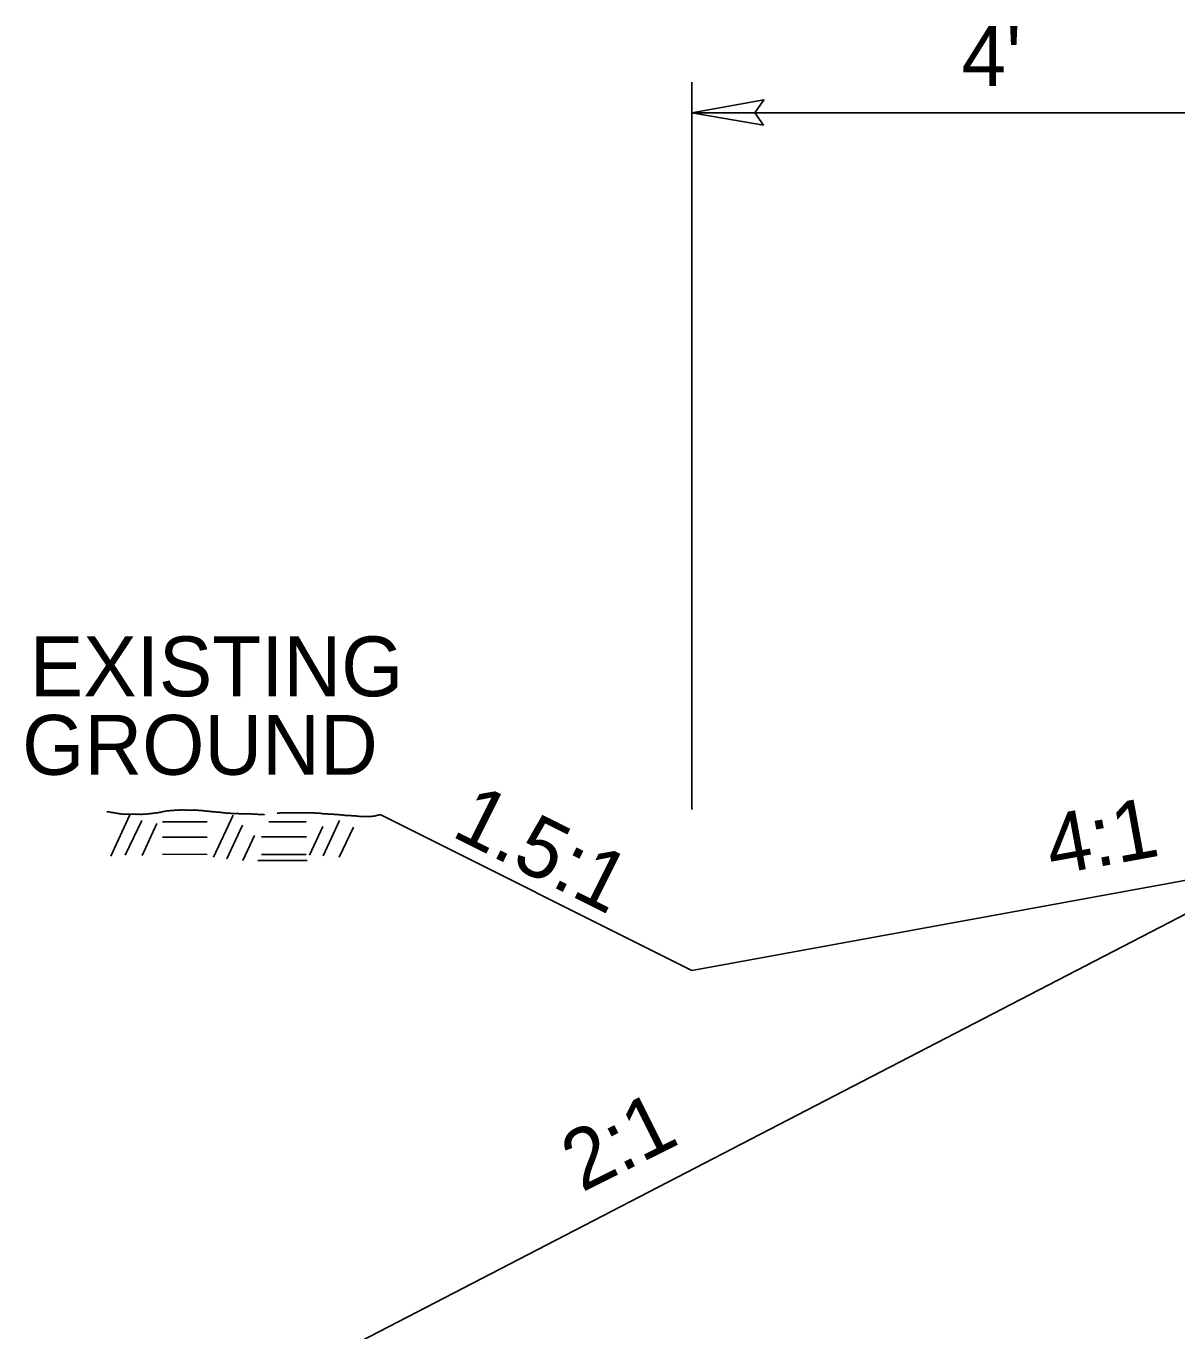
# Model space of a CAD drawing. Extents: x 1542177 to 1542464, y 45134 to 45344.
# Drawn here: x 1542276.79 to 1542288.32, y 45194.34 to 45207.43 of the extents above; entities that cross this region are included whole.
import ezdxf

# ---------------------------------------------------------------- set-up
doc = ezdxf.new("R2010")
doc.units = 0
doc.layers.add('Default', color=7, linetype='Continuous')

msp = doc.modelspace()

# ---------------------------------------------------------------- linework, layer by layer
at = {"layer": 'Default'}
for p, q in [((1542283.461, 45199.571), (1542283.461, 45206.867)), ((1542283.461, 45206.56), (1542289.373, 45206.56)), ((1542277.829, 45199.518), (1542277.638, 45199.104)), ((1542277.947, 45199.462), (1542277.782, 45199.114)), ((1542278.1, 45199.431), (1542277.952, 45199.112)), ((1542278.156, 45199.449), (1542278.603, 45199.448)), ((1542278.863, 45199.515), (1542278.666, 45199.093)), ((1542278.958, 45199.416), (1542278.802, 45199.078)), ((1542279.221, 45199.448), (1542279.597, 45199.448)), ((1542279.763, 45199.402), (1542279.628, 45199.113)), ((1542279.931, 45199.46), (1542279.766, 45199.106)), ((1542280.069, 45199.396), (1542279.928, 45199.093)), ((1542283.461, 45197.957), (1542280.336, 45199.52)), ((1542278.156, 45199.296), (1542278.604, 45199.296)), ((1542279.077, 45199.31), (1542278.961, 45199.06)), ((1542279.147, 45199.297), (1542279.598, 45199.297)), ((1542278.156, 45199.123), (1542278.604, 45199.122)), ((1542278.251, 45193.26), (1542289.419, 45199.047)), ((1542279.111, 45199.06), (1542279.605, 45199.06)), ((1542279.148, 45199.121), (1542279.596, 45199.121)), ((1542289.419, 45199.047), (1542283.461, 45197.957))]:
    msp.add_line(p, q, dxfattribs=at)
msp.add_lwpolyline([(1542284.181, 45206.436), (1542283.461, 45206.56), (1542284.185, 45206.688), (1542284.093, 45206.56)], close=True, dxfattribs=at)
for points in [[(1542277.599, 45199.547), (1542277.6, 45199.548), (1542277.601, 45199.549), (1542277.602, 45199.549), (1542277.604, 45199.55), (1542277.606, 45199.549), (1542277.608, 45199.549), (1542277.611, 45199.549), (1542277.614, 45199.55), (1542277.616, 45199.55), (1542277.619, 45199.549), (1542277.62, 45199.548), (1542277.623, 45199.547), (1542277.625, 45199.547), (1542277.627, 45199.546), (1542277.63, 45199.545), (1542277.633, 45199.545), (1542277.635, 45199.544), (1542277.638, 45199.544), (1542277.64, 45199.543), (1542277.642, 45199.542), (1542277.644, 45199.542), (1542277.646, 45199.541), (1542277.649, 45199.542), (1542277.652, 45199.542), (1542277.654, 45199.542), (1542277.657, 45199.54), (1542277.659, 45199.54), (1542277.662, 45199.54), (1542277.664, 45199.541), (1542277.667, 45199.54), (1542277.669, 45199.54), (1542277.672, 45199.539), (1542277.674, 45199.538), (1542277.676, 45199.538), (1542277.679, 45199.537), (1542277.681, 45199.536), (1542277.683, 45199.536), (1542277.686, 45199.535), (1542277.688, 45199.535), (1542277.691, 45199.535), (1542277.693, 45199.535), (1542277.696, 45199.535), (1542277.698, 45199.534), (1542277.7, 45199.534), (1542277.702, 45199.533), (1542277.705, 45199.532), (1542277.707, 45199.532), (1542277.71, 45199.531), (1542277.712, 45199.531), (1542277.715, 45199.532), (1542277.717, 45199.531), (1542277.72, 45199.53), (1542277.722, 45199.53), (1542277.724, 45199.529), (1542277.727, 45199.529), (1542277.729, 45199.528), (1542277.731, 45199.528), (1542277.734, 45199.527), (1542277.738, 45199.528), (1542277.741, 45199.528), (1542277.743, 45199.528), (1542277.745, 45199.526), (1542277.748, 45199.526), (1542277.752, 45199.525), (1542277.755, 45199.525), (1542277.759, 45199.526), (1542277.761, 45199.526), (1542277.764, 45199.526), (1542277.766, 45199.526), (1542277.769, 45199.526), (1542277.773, 45199.525), (1542277.776, 45199.525), (1542277.779, 45199.524), (1542277.781, 45199.524), (1542277.783, 45199.524), (1542277.787, 45199.524), (1542277.79, 45199.524), (1542277.794, 45199.524), (1542277.796, 45199.524), (1542277.799, 45199.524), (1542277.802, 45199.524), (1542277.805, 45199.524), (1542277.809, 45199.524), (1542277.813, 45199.524), (1542277.816, 45199.523), (1542277.82, 45199.524), (1542277.823, 45199.524), (1542277.826, 45199.524), (1542277.828, 45199.524), (1542277.831, 45199.525), (1542277.833, 45199.525), (1542277.835, 45199.524), (1542277.838, 45199.524), (1542277.841, 45199.524), (1542277.844, 45199.524), (1542277.848, 45199.524), (1542277.852, 45199.524), (1542277.856, 45199.524), (1542277.86, 45199.524), (1542277.862, 45199.524), (1542277.864, 45199.524), (1542277.866, 45199.524), (1542277.869, 45199.524), (1542277.873, 45199.524), (1542277.876, 45199.524), (1542277.879, 45199.524), (1542277.882, 45199.524), (1542277.885, 45199.524), (1542277.887, 45199.524), (1542277.889, 45199.523), (1542277.891, 45199.523), (1542277.894, 45199.523), (1542277.896, 45199.524), (1542277.898, 45199.524), (1542277.9, 45199.524), (1542277.902, 45199.524), (1542277.905, 45199.524), (1542277.907, 45199.524), (1542277.909, 45199.524), (1542277.912, 45199.524), (1542277.914, 45199.524), (1542277.917, 45199.524), (1542277.919, 45199.524), (1542277.922, 45199.524), (1542277.925, 45199.523), (1542277.927, 45199.523), (1542277.929, 45199.523), (1542277.932, 45199.523), (1542277.934, 45199.523), (1542277.936, 45199.523), (1542277.938, 45199.524), (1542277.94, 45199.524), (1542277.944, 45199.524), (1542277.948, 45199.523), (1542277.952, 45199.523), (1542277.954, 45199.523), (1542277.957, 45199.524), (1542277.959, 45199.524), (1542277.961, 45199.524), (1542277.963, 45199.524), (1542277.964, 45199.524), (1542277.969, 45199.524), (1542277.973, 45199.525), (1542277.977, 45199.526), (1542277.979, 45199.526), (1542277.981, 45199.526), (1542277.984, 45199.526), (1542277.987, 45199.526), (1542277.99, 45199.525), (1542277.994, 45199.525), (1542277.998, 45199.525), (1542278.002, 45199.528), (1542278.006, 45199.528), (1542278.009, 45199.528), (1542278.013, 45199.527), (1542278.016, 45199.527), (1542278.02, 45199.528), (1542278.023, 45199.528), (1542278.027, 45199.529), (1542278.03, 45199.53), (1542278.034, 45199.531), (1542278.037, 45199.531), (1542278.04, 45199.532), (1542278.044, 45199.531), (1542278.048, 45199.531), (1542278.05, 45199.532), (1542278.052, 45199.532), (1542278.055, 45199.533), (1542278.057, 45199.533), (1542278.06, 45199.534), (1542278.062, 45199.535), (1542278.066, 45199.535), (1542278.07, 45199.534), (1542278.074, 45199.535), (1542278.076, 45199.535), (1542278.079, 45199.535), (1542278.081, 45199.536), (1542278.084, 45199.536), (1542278.086, 45199.538), (1542278.088, 45199.538), (1542278.09, 45199.538), (1542278.092, 45199.538), (1542278.094, 45199.538), (1542278.1, 45199.539), (1542278.106, 45199.538), (1542278.111, 45199.54), (1542278.114, 45199.54), (1542278.117, 45199.541), (1542278.119, 45199.542), (1542278.122, 45199.542), (1542278.124, 45199.543), (1542278.127, 45199.544), (1542278.129, 45199.544), (1542278.131, 45199.543), (1542278.134, 45199.543), (1542278.137, 45199.544), (1542278.141, 45199.546), (1542278.145, 45199.547), (1542278.147, 45199.547), (1542278.15, 45199.547), (1542278.152, 45199.547), (1542278.156, 45199.548), (1542278.158, 45199.55), (1542278.162, 45199.551), (1542278.164, 45199.551), (1542278.167, 45199.55), (1542278.169, 45199.551), (1542278.172, 45199.551), (1542278.174, 45199.552), (1542278.176, 45199.553), (1542278.178, 45199.553), (1542278.181, 45199.554), (1542278.183, 45199.555), (1542278.186, 45199.555), (1542278.189, 45199.556), (1542278.191, 45199.556), (1542278.195, 45199.557), (1542278.198, 45199.557), (1542278.202, 45199.557), (1542278.204, 45199.558), (1542278.207, 45199.558), (1542278.209, 45199.558), (1542278.211, 45199.558), (1542278.213, 45199.56), (1542278.215, 45199.56), (1542278.218, 45199.56), (1542278.22, 45199.56), (1542278.223, 45199.56), (1542278.226, 45199.56), (1542278.228, 45199.56), (1542278.23, 45199.56), (1542278.234, 45199.56), (1542278.237, 45199.561), (1542278.241, 45199.561), (1542278.244, 45199.561), (1542278.246, 45199.561), (1542278.249, 45199.561), (1542278.251, 45199.561), (1542278.252, 45199.563), (1542278.254, 45199.563), (1542278.258, 45199.563), (1542278.263, 45199.563), (1542278.267, 45199.563), (1542278.269, 45199.563), (1542278.271, 45199.563), (1542278.273, 45199.563), (1542278.275, 45199.564), (1542278.277, 45199.565), (1542278.28, 45199.565), (1542278.282, 45199.565), (1542278.285, 45199.565), (1542278.287, 45199.565), (1542278.29, 45199.565), (1542278.292, 45199.565), (1542278.294, 45199.565), (1542278.296, 45199.565), (1542278.299, 45199.565), (1542278.301, 45199.565), (1542278.303, 45199.565), (1542278.305, 45199.565), (1542278.307, 45199.565), (1542278.31, 45199.565), (1542278.313, 45199.566), (1542278.316, 45199.567), (1542278.318, 45199.567), (1542278.32, 45199.566), (1542278.322, 45199.566), (1542278.325, 45199.566), (1542278.328, 45199.567), (1542278.331, 45199.567), (1542278.332, 45199.567), (1542278.334, 45199.566), (1542278.336, 45199.566), (1542278.34, 45199.566), (1542278.345, 45199.567), (1542278.349, 45199.567), (1542278.353, 45199.567), (1542278.357, 45199.567), (1542278.361, 45199.567), (1542278.364, 45199.567), (1542278.367, 45199.566), (1542278.369, 45199.566), (1542278.376, 45199.566), (1542278.384, 45199.567), (1542278.391, 45199.567), (1542278.393, 45199.567), (1542278.395, 45199.566), (1542278.397, 45199.566), (1542278.399, 45199.566), (1542278.402, 45199.566), (1542278.404, 45199.566), (1542278.407, 45199.566), (1542278.409, 45199.566), (1542278.411, 45199.566), (1542278.414, 45199.566), (1542278.416, 45199.566), (1542278.419, 45199.566), (1542278.423, 45199.566), (1542278.426, 45199.566), (1542278.43, 45199.566), (1542278.433, 45199.566), (1542278.435, 45199.566), (1542278.438, 45199.566), (1542278.44, 45199.566), (1542278.442, 45199.566), (1542278.445, 45199.566), (1542278.447, 45199.566), (1542278.449, 45199.566), (1542278.452, 45199.566), (1542278.454, 45199.566), (1542278.456, 45199.566), (1542278.459, 45199.566), (1542278.461, 45199.566), (1542278.463, 45199.566), (1542278.466, 45199.566), (1542278.468, 45199.566), (1542278.47, 45199.567), (1542278.473, 45199.567), (1542278.475, 45199.567), (1542278.477, 45199.567), (1542278.479, 45199.567), (1542278.482, 45199.566), (1542278.486, 45199.565), (1542278.49, 45199.565), (1542278.492, 45199.565), (1542278.495, 45199.565), (1542278.498, 45199.565), (1542278.5, 45199.565), (1542278.502, 45199.565), (1542278.505, 45199.565), (1542278.507, 45199.565), (1542278.509, 45199.565), (1542278.511, 45199.565), (1542278.514, 45199.565), (1542278.516, 45199.563), (1542278.518, 45199.563), (1542278.521, 45199.563), (1542278.524, 45199.563), (1542278.526, 45199.563), (1542278.529, 45199.563), (1542278.531, 45199.563), (1542278.534, 45199.563), (1542278.537, 45199.563), (1542278.541, 45199.563), (1542278.544, 45199.563), (1542278.547, 45199.562), (1542278.549, 45199.561), (1542278.552, 45199.561), (1542278.554, 45199.561), (1542278.556, 45199.561), (1542278.558, 45199.561), (1542278.56, 45199.56), (1542278.563, 45199.559), (1542278.565, 45199.559), (1542278.581, 45199.557), (1542278.596, 45199.555), (1542278.611, 45199.554), (1542278.614, 45199.554), (1542278.616, 45199.554), (1542278.618, 45199.554), (1542278.621, 45199.554), (1542278.624, 45199.552), (1542278.626, 45199.552), (1542278.628, 45199.552), (1542278.63, 45199.552), (1542278.632, 45199.552), (1542278.635, 45199.552), (1542278.637, 45199.553), (1542278.64, 45199.552), (1542278.642, 45199.552), (1542278.645, 45199.551), (1542278.647, 45199.551), (1542278.649, 45199.55), (1542278.652, 45199.55), (1542278.654, 45199.55), (1542278.66, 45199.55), (1542278.666, 45199.55), (1542278.672, 45199.55), (1542278.675, 45199.55), (1542278.677, 45199.549), (1542278.68, 45199.549), (1542278.682, 45199.548), (1542278.684, 45199.549), (1542278.687, 45199.548), (1542278.689, 45199.548), (1542278.692, 45199.547), (1542278.694, 45199.546), (1542278.702, 45199.546), (1542278.71, 45199.546), (1542278.718, 45199.545), (1542278.725, 45199.544), (1542278.732, 45199.544), (1542278.739, 45199.543), (1542278.743, 45199.543), (1542278.746, 45199.542), (1542278.75, 45199.542), (1542278.754, 45199.541), (1542278.758, 45199.54), (1542278.761, 45199.54), (1542278.764, 45199.539), (1542278.767, 45199.54), (1542278.769, 45199.54), (1542278.771, 45199.54), (1542278.774, 45199.538), (1542278.776, 45199.538), (1542278.778, 45199.537), (1542278.78, 45199.538), (1542278.782, 45199.538), (1542278.785, 45199.538), (1542278.787, 45199.536), (1542278.79, 45199.536), (1542278.793, 45199.536), (1542278.797, 45199.536), (1542278.801, 45199.536), (1542278.803, 45199.535), (1542278.806, 45199.535), (1542278.808, 45199.535), (1542278.811, 45199.534), (1542278.814, 45199.534), (1542278.817, 45199.534), (1542278.822, 45199.534), (1542278.828, 45199.535), (1542278.834, 45199.534), (1542278.837, 45199.534), (1542278.841, 45199.533), (1542278.844, 45199.533), (1542278.847, 45199.533), (1542278.849, 45199.532), (1542278.851, 45199.532), (1542278.857, 45199.532), (1542278.862, 45199.532), (1542278.868, 45199.532), (1542278.87, 45199.532), (1542278.873, 45199.532), (1542278.875, 45199.532), (1542278.877, 45199.532), (1542278.88, 45199.531), (1542278.882, 45199.531), (1542278.885, 45199.53), (1542278.887, 45199.53), (1542278.889, 45199.53), (1542278.896, 45199.53), (1542278.902, 45199.531), (1542278.908, 45199.531), (1542278.91, 45199.531), (1542278.912, 45199.531), (1542278.915, 45199.531), (1542278.917, 45199.531), (1542278.92, 45199.529), (1542278.922, 45199.529), (1542278.925, 45199.528), (1542278.927, 45199.528), (1542278.93, 45199.528), (1542278.936, 45199.528), (1542278.942, 45199.528), (1542278.947, 45199.529), (1542278.95, 45199.529), (1542278.952, 45199.529), (1542278.954, 45199.529), (1542278.957, 45199.529), (1542278.96, 45199.529), (1542278.963, 45199.529), (1542278.968, 45199.529), (1542278.973, 45199.527), (1542278.979, 45199.527), (1542278.981, 45199.527), (1542278.983, 45199.527), (1542278.985, 45199.527), (1542278.99, 45199.527), (1542278.995, 45199.527), (1542279, 45199.527), (1542279.002, 45199.527), (1542279.005, 45199.527), (1542279.008, 45199.527), (1542279.014, 45199.527), (1542279.02, 45199.527), (1542279.026, 45199.527), (1542279.034, 45199.527), (1542279.043, 45199.527), (1542279.051, 45199.527), (1542279.057, 45199.527), (1542279.063, 45199.524), (1542279.069, 45199.525), (1542279.071, 45199.525), (1542279.073, 45199.525), (1542279.075, 45199.525), (1542279.077, 45199.525), (1542279.08, 45199.525), (1542279.083, 45199.525), (1542279.089, 45199.525), (1542279.095, 45199.525), (1542279.101, 45199.525), (1542279.103, 45199.525), (1542279.105, 45199.525), (1542279.108, 45199.525), (1542279.11, 45199.525), (1542279.112, 45199.523), (1542279.114, 45199.523), (1542279.117, 45199.523), (1542279.12, 45199.523), (1542279.122, 45199.523), (1542279.124, 45199.523), (1542279.126, 45199.523), (1542279.128, 45199.523), (1542279.131, 45199.523), (1542279.133, 45199.523), (1542279.136, 45199.523), (1542279.138, 45199.523), (1542279.141, 45199.522), (1542279.143, 45199.521), (1542279.146, 45199.521), (1542279.149, 45199.521), (1542279.152, 45199.521), (1542279.154, 45199.521), (1542279.156, 45199.522), (1542279.158, 45199.522), (1542279.16, 45199.522), (1542279.163, 45199.522), (1542279.165, 45199.522), (1542279.168, 45199.521), (1542279.17, 45199.522), (1542279.173, 45199.522), (1542279.175, 45199.522), (1542279.177, 45199.519), (1542279.179, 45199.519), (1542279.179, 45199.519), (1542279.179, 45199.519), (1542279.179, 45199.519)], [(1542279.304, 45199.534), (1542279.306, 45199.535), (1542279.309, 45199.535), (1542279.312, 45199.535), (1542279.317, 45199.536), (1542279.323, 45199.535), (1542279.329, 45199.536), (1542279.331, 45199.536), (1542279.333, 45199.538), (1542279.335, 45199.538), (1542279.341, 45199.538), (1542279.347, 45199.537), (1542279.353, 45199.537), (1542279.362, 45199.537), (1542279.37, 45199.537), (1542279.379, 45199.537), (1542279.385, 45199.537), (1542279.391, 45199.539), (1542279.397, 45199.539), (1542279.403, 45199.54), (1542279.409, 45199.539), (1542279.415, 45199.539), (1542279.417, 45199.539), (1542279.419, 45199.539), (1542279.421, 45199.539), (1542279.427, 45199.54), (1542279.433, 45199.539), (1542279.438, 45199.539), (1542279.441, 45199.539), (1542279.443, 45199.54), (1542279.446, 45199.54), (1542279.452, 45199.54), (1542279.458, 45199.539), (1542279.464, 45199.539), (1542279.467, 45199.539), (1542279.469, 45199.539), (1542279.472, 45199.539), (1542279.474, 45199.539), (1542279.477, 45199.539), (1542279.48, 45199.539), (1542279.485, 45199.539), (1542279.49, 45199.539), (1542279.496, 45199.539), (1542279.502, 45199.539), (1542279.508, 45199.539), (1542279.514, 45199.539), (1542279.517, 45199.539), (1542279.521, 45199.539), (1542279.524, 45199.539), (1542279.529, 45199.539), (1542279.534, 45199.539), (1542279.539, 45199.539), (1542279.542, 45199.539), (1542279.544, 45199.539), (1542279.547, 45199.539), (1542279.549, 45199.539), (1542279.551, 45199.539), (1542279.553, 45199.539), (1542279.556, 45199.539), (1542279.559, 45199.539), (1542279.561, 45199.539), (1542279.564, 45199.539), (1542279.566, 45199.539), (1542279.568, 45199.539), (1542279.571, 45199.539), (1542279.575, 45199.539), (1542279.579, 45199.539), (1542279.581, 45199.539), (1542279.584, 45199.539), (1542279.586, 45199.539), (1542279.589, 45199.539), (1542279.591, 45199.539), (1542279.593, 45199.539), (1542279.596, 45199.539), (1542279.598, 45199.539), (1542279.6, 45199.539), (1542279.602, 45199.539), (1542279.604, 45199.539), (1542279.607, 45199.539), (1542279.608, 45199.539), (1542279.61, 45199.539), (1542279.612, 45199.539), (1542279.615, 45199.539), (1542279.617, 45199.539), (1542279.62, 45199.539), (1542279.623, 45199.539), (1542279.625, 45199.539), (1542279.628, 45199.539), (1542279.631, 45199.539), (1542279.633, 45199.539), (1542279.636, 45199.539), (1542279.64, 45199.539), (1542279.643, 45199.539), (1542279.646, 45199.539), (1542279.651, 45199.539), (1542279.656, 45199.539), (1542279.661, 45199.539), (1542279.663, 45199.538), (1542279.666, 45199.539), (1542279.668, 45199.539), (1542279.671, 45199.539), (1542279.673, 45199.536), (1542279.675, 45199.536), (1542279.677, 45199.536), (1542279.68, 45199.537), (1542279.682, 45199.537), (1542279.69, 45199.537), (1542279.698, 45199.535), (1542279.707, 45199.535), (1542279.713, 45199.536), (1542279.719, 45199.536), (1542279.725, 45199.536), (1542279.727, 45199.536), (1542279.729, 45199.536), (1542279.731, 45199.536), (1542279.734, 45199.536), (1542279.737, 45199.535), (1542279.739, 45199.534), (1542279.742, 45199.533), (1542279.744, 45199.532), (1542279.747, 45199.532), (1542279.749, 45199.531), (1542279.751, 45199.532), (1542279.753, 45199.531), (1542279.755, 45199.531), (1542279.758, 45199.53), (1542279.76, 45199.53), (1542279.766, 45199.529), (1542279.773, 45199.53), (1542279.779, 45199.53), (1542279.782, 45199.529), (1542279.785, 45199.528), (1542279.789, 45199.528), (1542279.792, 45199.527), (1542279.795, 45199.528), (1542279.797, 45199.528), (1542279.801, 45199.528), (1542279.804, 45199.529), (1542279.807, 45199.529), (1542279.81, 45199.529), (1542279.812, 45199.527), (1542279.814, 45199.527), (1542279.819, 45199.526), (1542279.824, 45199.526), (1542279.829, 45199.526), (1542279.831, 45199.526), (1542279.833, 45199.525), (1542279.836, 45199.525), (1542279.838, 45199.525), (1542279.84, 45199.525), (1542279.842, 45199.525), (1542279.845, 45199.525), (1542279.847, 45199.525), (1542279.849, 45199.525), (1542279.855, 45199.525), (1542279.861, 45199.525), (1542279.866, 45199.525), (1542279.869, 45199.525), (1542279.872, 45199.524), (1542279.874, 45199.523), (1542279.877, 45199.523), (1542279.879, 45199.523), (1542279.882, 45199.523), (1542279.885, 45199.523), (1542279.887, 45199.523), (1542279.89, 45199.522), (1542279.892, 45199.522), (1542279.894, 45199.52), (1542279.896, 45199.52), (1542279.898, 45199.52), (1542279.901, 45199.521), (1542279.903, 45199.521), (1542279.905, 45199.521), (1542279.908, 45199.521), (1542279.911, 45199.522), (1542279.913, 45199.522), (1542279.916, 45199.521), (1542279.918, 45199.521), (1542279.92, 45199.521), (1542279.923, 45199.519), (1542279.925, 45199.519), (1542279.927, 45199.519), (1542279.929, 45199.519), (1542279.931, 45199.519), (1542279.934, 45199.519), (1542279.936, 45199.52), (1542279.939, 45199.52), (1542279.941, 45199.52), (1542279.944, 45199.518), (1542279.946, 45199.517), (1542279.949, 45199.517), (1542279.953, 45199.517), (1542279.957, 45199.517), (1542279.959, 45199.517), (1542279.961, 45199.516), (1542279.964, 45199.516), (1542279.967, 45199.515), (1542279.971, 45199.517), (1542279.975, 45199.516), (1542279.977, 45199.516), (1542279.978, 45199.514), (1542279.981, 45199.514), (1542279.984, 45199.513), (1542279.988, 45199.512), (1542279.992, 45199.512), (1542279.995, 45199.512), (1542279.999, 45199.513), (1542280.002, 45199.513), (1542280.005, 45199.513), (1542280.008, 45199.513), (1542280.01, 45199.512), (1542280.019, 45199.512), (1542280.027, 45199.511), (1542280.035, 45199.51), (1542280.039, 45199.51), (1542280.042, 45199.51), (1542280.045, 45199.51), (1542280.048, 45199.51), (1542280.051, 45199.509), (1542280.053, 45199.508), (1542280.055, 45199.508), (1542280.058, 45199.508), (1542280.06, 45199.508), (1542280.062, 45199.508), (1542280.065, 45199.508), (1542280.068, 45199.508), (1542280.071, 45199.508), (1542280.075, 45199.507), (1542280.079, 45199.507), (1542280.081, 45199.507), (1542280.083, 45199.507), (1542280.085, 45199.507), (1542280.087, 45199.507), (1542280.09, 45199.507), (1542280.093, 45199.507), (1542280.096, 45199.507), (1542280.099, 45199.505), (1542280.103, 45199.505), (1542280.105, 45199.505), (1542280.107, 45199.505), (1542280.11, 45199.505), (1542280.112, 45199.505), (1542280.115, 45199.505), (1542280.118, 45199.505), (1542280.122, 45199.505), (1542280.125, 45199.503), (1542280.128, 45199.503), (1542280.13, 45199.503), (1542280.133, 45199.503), (1542280.135, 45199.503), (1542280.138, 45199.503), (1542280.14, 45199.503), (1542280.143, 45199.503), (1542280.152, 45199.503), (1542280.162, 45199.501), (1542280.171, 45199.501), (1542280.177, 45199.501), (1542280.183, 45199.501), (1542280.188, 45199.501), (1542280.191, 45199.501), (1542280.193, 45199.501), (1542280.196, 45199.501), (1542280.198, 45199.501), (1542280.2, 45199.501), (1542280.203, 45199.501), (1542280.209, 45199.501), (1542280.215, 45199.501), (1542280.221, 45199.501), (1542280.223, 45199.501), (1542280.225, 45199.503), (1542280.227, 45199.503), (1542280.233, 45199.503), (1542280.24, 45199.503), (1542280.247, 45199.503), (1542280.249, 45199.503), (1542280.251, 45199.503), (1542280.253, 45199.503), (1542280.255, 45199.503), (1542280.257, 45199.505), (1542280.26, 45199.505), (1542280.266, 45199.506), (1542280.272, 45199.504), (1542280.278, 45199.505), (1542280.28, 45199.506), (1542280.282, 45199.506), (1542280.284, 45199.507), (1542280.286, 45199.507), (1542280.289, 45199.508), (1542280.291, 45199.509), (1542280.294, 45199.509), (1542280.296, 45199.51), (1542280.299, 45199.51), (1542280.303, 45199.511), (1542280.307, 45199.513), (1542280.311, 45199.514), (1542280.313, 45199.515), (1542280.316, 45199.513), (1542280.318, 45199.514), (1542280.321, 45199.515), (1542280.323, 45199.516), (1542280.325, 45199.516), (1542280.327, 45199.517), (1542280.329, 45199.518), (1542280.332, 45199.519), (1542280.333, 45199.52), (1542280.334, 45199.52), (1542280.336, 45199.52)]]:
    msp.add_open_spline(points, degree=3, dxfattribs=at)

# ---------------------------------------------------------------- texts
for s, p in [("4'", (1542286.166, 45206.828)), ('EXISTING', (1542276.826, 45200.707)), ('GROUND', (1542276.748, 45199.92))]:
    msp.add_text(s, height=0.6, dxfattribs=at).set_placement(p)
for s, rotation, p in [('1.5:1', 333.4349, (1542281.037, 45199.311)), ('4:1', 10.3648, (1542287.072, 45198.911)), ('2:1', 26.565, (1542282.359, 45195.728))]:
    msp.add_text(s, height=0.6, rotation=rotation, dxfattribs=at).set_placement(p)

doc.saveas('drawing.dxf')
